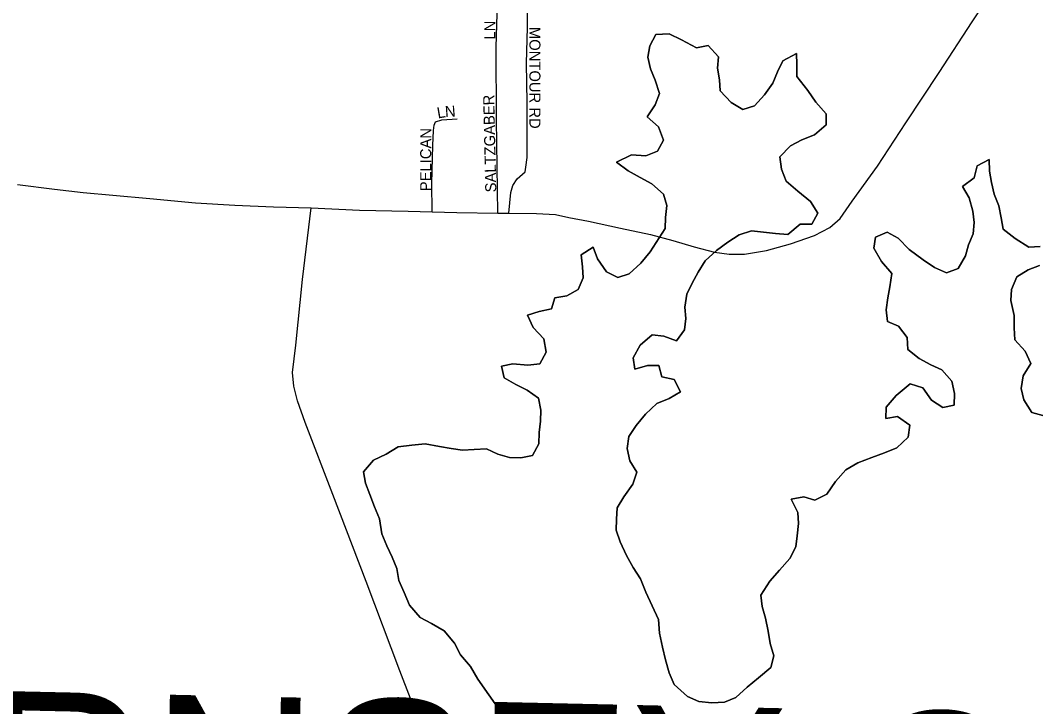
# Model space of a CAD drawing. Extents: x -22 to 431, y -18 to 160.
# Drawn here: x 329.532 to 330.402, y 158.932 to 159.52 of the extents above; entities that cross this region are included whole.
import ezdxf

# ---------------------------------------------------------------- set-up
doc = ezdxf.new("R2010")
doc.units = 0
for name, color, linetype in [('GM_X_County_ROW', 7, 'Continuous'), ('GM_X_County_Subdivision', 7, 'Continuous'), ('GM_X_Township_ROW', 7, 'Continuous'), ('GM_X_Township_Subdivision', 7, 'Continuous'), ('GM_X_Unincorporated_Text', 7, 'Continuous')]:
    doc.layers.add(name, color=color, linetype=linetype)

msp = doc.modelspace()

# ---------------------------------------------------------------- linework, layer by layer
at = {"layer": 'GM_X_County_ROW'}
for points in [[(329.52949, 159.37947), (329.56105, 159.37544), (329.58577, 159.37243), (329.61124, 159.37019), (329.64279, 159.36729), (329.68194, 159.36377), (329.71575, 159.36167), (329.74879, 159.36031), (329.78107, 159.35933), (329.82247, 159.35735), (329.86423, 159.35653), (329.88487, 159.35593), (329.906, 159.35532), (329.94107, 159.35479), (329.94206, 159.35478), (329.95051, 159.35472), (329.97432, 159.35455), (329.99065, 159.35368), (330.00208, 159.35121), (330.01884, 159.34807), (330.04626, 159.34206), (330.07217, 159.33641), (330.09123, 159.33141), (330.10954, 159.32601), (330.12707, 159.32136), (330.13963, 159.31967), (330.15254, 159.3195), (330.17145, 159.32286), (330.19223, 159.32852), (330.2126, 159.33569), (330.22577, 159.34237), (330.23475, 159.35011), (330.24512, 159.3651), (330.26661, 159.39509), (330.29103, 159.43234), (330.31951, 159.47537), (330.34799, 159.51877), (330.37389, 159.55795)], [(329.94924, 158.73153), (329.93725, 158.76413), (329.91055, 158.8213), (329.88469, 158.89114), (329.85729, 158.96248), (329.82828, 159.03911), (329.79969, 159.11347), (329.77586, 159.17537), (329.76947, 159.19388), (329.76622, 159.20636), (329.76526, 159.21813), (329.76789, 159.24172), (329.77376, 159.29804), (329.78107, 159.35933)]]:
    msp.add_lwpolyline(points, dxfattribs=at)
at = {"layer": 'GM_X_Township_ROW'}
for points in [[(329.95051, 159.35472), (329.95222, 159.37239), (329.95406, 159.37847), (329.95779, 159.38419), (329.96455, 159.39032), (329.96526, 159.39412), (329.96641, 159.40251), (329.96629, 159.44967), (329.9657, 159.48326), (329.9666, 159.51403), (329.96672, 159.5657), (329.96671, 159.58067), (329.96681, 159.5969), (329.96693, 159.59938), (329.97924, 159.60181), (329.99294, 159.60755), (329.99854, 159.61595), (330.00001, 159.62127)], [(329.94107, 159.35479), (329.93997, 159.43489), (329.93983, 159.49711), (329.94161, 159.55478), (329.94237, 159.59767), (329.89359, 159.59955), (329.89359, 159.55554), (329.94123, 159.55478)], [(329.88487, 159.35593), (329.88449, 159.38057), (329.88535, 159.41283), (329.886, 159.42573), (329.88671, 159.43029), (329.88782, 159.43296), (329.8931, 159.43489), (329.90632, 159.43576)]]:
    msp.add_lwpolyline(points, dxfattribs=at)
at = {"layer": 'GM_X_Township_Subdivision'}
for points in [[(330.18554, 159.48538), (330.1811, 159.47584), (330.17704, 159.46631), (330.16995, 159.45636), (330.16135, 159.44677), (330.15117, 159.44361), (330.14127, 159.44956), (330.13171, 159.45968), (330.13123, 159.46915), (330.12961, 159.479), (330.13026, 159.48886), (330.12145, 159.49862), (330.11164, 159.4966), (330.0987, 159.50326), (330.08805, 159.50844), (330.07671, 159.50792), (330.07151, 159.49838), (330.06973, 159.48849), (330.0721, 159.47866), (330.07599, 159.46885), (330.0799, 159.45752), (330.07622, 159.44761), (330.06914, 159.43728), (330.07907, 159.42868), (330.08335, 159.41736), (330.07816, 159.40781), (330.06798, 159.40389), (330.05586, 159.40488), (330.04306, 159.39865), (330.05298, 159.39119), (330.06326, 159.38525), (330.07315, 159.38006), (330.08309, 159.37108), (330.08622, 159.36126), (330.08481, 159.351), (330.08454, 159.34152), (330.07188, 159.32164), (330.06366, 159.31206), (330.05392, 159.30283), (330.04412, 159.29968), (330.03423, 159.30448), (330.02654, 159.31577), (330.02303, 159.32558), (330.01251, 159.31901), (330.01376, 159.30878), (330.01424, 159.29931), (330.01018, 159.28939), (330.0004, 159.28396), (329.9902, 159.28232), (329.98728, 159.2728), (329.97671, 159.2704), (329.96653, 159.26724), (329.97156, 159.25668), (329.98074, 159.24693), (329.98275, 159.23558), (329.97718, 159.22565), (329.96698, 159.22438), (329.9541, 159.22574), (329.94429, 159.22372), (329.94667, 159.21351), (329.95656, 159.20795), (329.96645, 159.20314), (329.97598, 159.19605), (329.97798, 159.18584), (329.97771, 159.17635), (329.97667, 159.16686), (329.9764, 159.157), (329.97083, 159.14707), (329.96101, 159.14505), (329.95117, 159.14531), (329.94131, 159.14822), (329.93142, 159.15264), (329.92083, 159.15213), (329.911, 159.15163), (329.90115, 159.15303), (329.89129, 159.1548), (329.87878, 159.15692), (329.86744, 159.15602), (329.85573, 159.15436), (329.84558, 159.14817), (329.83466, 159.1431), (329.82607, 159.13313), (329.82769, 159.12329), (329.83157, 159.11348), (329.83547, 159.10291), (329.83974, 159.09272), (329.84177, 159.07985), (329.84604, 159.06967), (329.85068, 159.05986), (329.85457, 159.05005), (329.85619, 159.03983), (329.86084, 159.02965), (329.8655, 159.01872), (329.87469, 159.00821), (329.8842, 159.00302), (329.89524, 158.99671), (329.90406, 158.9862), (329.90908, 158.97602), (329.91789, 158.96627), (329.92406, 158.95535), (329.94288, 158.92828)], [(329.94288, 158.92828), (329.92406, 158.95535), (329.91789, 158.96627), (329.90908, 158.97602), (329.90406, 158.9862), (329.89524, 158.99671), (329.8842, 159.00302), (329.87469, 159.00821), (329.8655, 159.01872), (329.86084, 159.02965), (329.85619, 159.03983), (329.85457, 159.05005), (329.85068, 159.05986), (329.84604, 159.06967), (329.84177, 159.07985), (329.83974, 159.09272), (329.83547, 159.10291), (329.83157, 159.11348), (329.82769, 159.12329), (329.82607, 159.13313), (329.83466, 159.1431), (329.84558, 159.14817), (329.85573, 159.15436), (329.86744, 159.15602), (329.87878, 159.15692), (329.89129, 159.1548), (329.90115, 159.15303), (329.911, 159.15163), (329.92083, 159.15213), (329.93142, 159.15264), (329.94131, 159.14822), (329.95117, 159.14531), (329.96101, 159.14505), (329.97083, 159.14707), (329.9764, 159.157), (329.97667, 159.16686), (329.97771, 159.17635), (329.97798, 159.18584), (329.97598, 159.19605), (329.96645, 159.20314), (329.95656, 159.20795), (329.94667, 159.21351), (329.94429, 159.22372), (329.9541, 159.22574), (329.96698, 159.22438), (329.97718, 159.22565), (329.98275, 159.23558), (329.98074, 159.24693), (329.97156, 159.25668), (329.96653, 159.26724), (329.97671, 159.2704), (329.98728, 159.2728), (329.9902, 159.28232), (330.0004, 159.28396), (330.01018, 159.28939), (330.01424, 159.29931), (330.01376, 159.30878), (330.01251, 159.31901), (330.02303, 159.32558), (330.02654, 159.31577), (330.03423, 159.30448), (330.04412, 159.29968), (330.05392, 159.30283), (330.06366, 159.31206), (330.07188, 159.32164), (330.08454, 159.34152), (330.08481, 159.351), (330.08622, 159.36126), (330.08309, 159.37108), (330.07315, 159.38006), (330.06326, 159.38525), (330.05298, 159.39119), (330.04306, 159.39865), (330.05586, 159.40488), (330.06798, 159.40389), (330.07816, 159.40781), (330.08335, 159.41736), (330.07907, 159.42868), (330.06914, 159.43728), (330.07622, 159.44761), (330.0799, 159.45752), (330.07599, 159.46885), (330.0721, 159.47866), (330.06973, 159.48849), (330.07151, 159.49838), (330.07671, 159.50792), (330.08805, 159.50844), (330.0987, 159.50326), (330.11164, 159.4966), (330.12145, 159.49862), (330.13026, 159.48886), (330.12961, 159.479), (330.13123, 159.46915), (330.13171, 159.45968), (330.14127, 159.44956), (330.15117, 159.44361), (330.16135, 159.44677), (330.16995, 159.45636), (330.17704, 159.46631), (330.1811, 159.47584), (330.18554, 159.48538)], [(330.29443, 159.17307), (330.29302, 159.16282), (330.28328, 159.15359), (330.27274, 159.14929), (330.2618, 159.14536), (330.24975, 159.14066), (330.23959, 159.13485), (330.23062, 159.12488), (330.22317, 159.11379), (330.21301, 159.10873), (330.20352, 159.11165), (330.19257, 159.10962), (330.19836, 159.09831), (330.19884, 159.08884), (330.19782, 159.07821), (330.19679, 159.06871), (330.19159, 159.05879), (330.18262, 159.04882), (330.1744, 159.03924), (330.16658, 159.02738), (330.16782, 159.01754), (330.17057, 159.00771), (330.17296, 158.99636), (330.17459, 158.98577), (330.17773, 158.97519), (330.17518, 158.9653), (330.16468, 158.95644), (330.15493, 158.94836), (330.14519, 158.93952), (330.13539, 158.9356), (330.1248, 158.93509), (330.11344, 158.93609), (330.10393, 158.94052), (330.09248, 158.95062), (330.08821, 158.9608), (330.08506, 158.97176), (330.0823, 158.98273), (330.0799, 158.99483), (330.07902, 159.00657), (330.06818, 159.02995), (330.06352, 159.04127), (330.05736, 159.05106), (330.05157, 159.06122), (330.04615, 159.07291), (330.04264, 159.08311), (330.04292, 159.09259), (330.04357, 159.10208), (330.04915, 159.11163), (330.05698, 159.12235), (330.06028, 159.13263), (330.0545, 159.14242), (330.05211, 159.153), (330.05352, 159.16326), (330.05985, 159.17282), (330.06769, 159.1824), (330.07743, 159.19162), (330.08798, 159.19593), (330.09775, 159.20174), (330.09235, 159.21229), (330.08173, 159.21443), (330.07935, 159.22426), (330.06952, 159.22414), (330.05858, 159.22097), (330.05734, 159.23082), (330.06328, 159.24151), (330.0734, 159.25036), (330.08363, 159.24935), (330.09426, 159.24531), (330.10135, 159.25488), (330.10238, 159.26437), (330.10152, 159.27422), (330.1033, 159.28524), (330.10774, 159.29478), (330.11293, 159.30432), (330.11888, 159.31388), (330.12863, 159.32272), (330.13839, 159.33005), (330.14816, 159.33624), (330.15871, 159.33978), (330.16894, 159.33839), (330.17917, 159.33738), (330.18977, 159.33637), (330.20028, 159.34523), (330.21049, 159.34536), (330.21568, 159.3549), (330.20915, 159.36468), (330.19846, 159.37365), (330.18853, 159.38225), (330.18426, 159.39244), (330.18301, 159.40304), (330.19199, 159.41264), (330.20177, 159.41769), (330.2127, 159.422), (330.22282, 159.43047), (330.22272, 159.43995), (330.21391, 159.45008), (330.207, 159.45985), (330.19741, 159.47187), (330.19768, 159.48211), (330.1972, 159.49159), (330.18554, 159.48538)], [(330.18554, 159.48538), (330.1972, 159.49159), (330.19768, 159.48211), (330.19741, 159.47187), (330.207, 159.45985), (330.21391, 159.45008), (330.22272, 159.43995), (330.22282, 159.43047), (330.2127, 159.422), (330.20177, 159.41769), (330.19199, 159.41264), (330.18301, 159.40304), (330.18426, 159.39244), (330.18853, 159.38225), (330.19846, 159.37365), (330.20915, 159.36468), (330.21568, 159.3549), (330.21049, 159.34536), (330.20028, 159.34523), (330.18977, 159.33637), (330.17917, 159.33738), (330.16894, 159.33839), (330.15871, 159.33978), (330.14816, 159.33624), (330.13839, 159.33005), (330.12863, 159.32272), (330.11888, 159.31388), (330.11293, 159.30432), (330.10774, 159.29478), (330.1033, 159.28524), (330.10152, 159.27422), (330.10238, 159.26437), (330.10135, 159.25488), (330.09426, 159.24531), (330.08363, 159.24935), (330.0734, 159.25036), (330.06328, 159.24151), (330.05734, 159.23082), (330.05858, 159.22097), (330.06952, 159.22414), (330.07935, 159.22426), (330.08173, 159.21443), (330.09235, 159.21229), (330.09775, 159.20174), (330.08798, 159.19593), (330.07743, 159.19162), (330.06769, 159.1824), (330.05985, 159.17282), (330.05352, 159.16326), (330.05211, 159.153), (330.0545, 159.14242), (330.06028, 159.13263), (330.05698, 159.12235), (330.04915, 159.11163), (330.04357, 159.10208), (330.04292, 159.09259), (330.04264, 159.08311), (330.04615, 159.07291), (330.05157, 159.06122), (330.05736, 159.05106), (330.06352, 159.04127), (330.06818, 159.02995), (330.07902, 159.00657), (330.0799, 158.99483), (330.0823, 158.98273), (330.08506, 158.97176), (330.08821, 158.9608), (330.09248, 158.95062), (330.10393, 158.94052), (330.11344, 158.93609), (330.1248, 158.93509), (330.13539, 158.9356), (330.14519, 158.93952), (330.15493, 158.94836), (330.16468, 158.95644), (330.17518, 158.9653), (330.17773, 158.97519), (330.17459, 158.98577), (330.17296, 158.99636), (330.17057, 159.00771), (330.16782, 159.01754), (330.16658, 159.02738), (330.1744, 159.03924), (330.18262, 159.04882), (330.19159, 159.05879), (330.19679, 159.06871), (330.19782, 159.07821), (330.19884, 159.08884), (330.19836, 159.09831), (330.19257, 159.10962), (330.20352, 159.11165), (330.21301, 159.10873), (330.22317, 159.11379), (330.23062, 159.12488), (330.23959, 159.13485), (330.24975, 159.14066), (330.2618, 159.14536), (330.27274, 159.14929), (330.28328, 159.15359), (330.29302, 159.16282), (330.29443, 159.17307)], [(330.4063, 159.32616), (330.39647, 159.32566), (330.38466, 159.3331), (330.37436, 159.34094), (330.37274, 159.35078), (330.37074, 159.361), (330.36685, 159.37119), (330.36448, 159.38102), (330.36286, 159.39086), (330.36237, 159.40071), (330.35222, 159.39528), (330.34968, 159.38501), (330.33954, 159.37768), (330.34532, 159.36789), (330.34847, 159.35655), (330.34971, 159.3467), (330.34867, 159.33721), (330.34461, 159.32767), (330.34207, 159.31816), (330.33575, 159.30746), (330.32595, 159.30355), (330.31569, 159.30835), (330.30578, 159.31468), (330.29396, 159.32363), (330.2844, 159.33338), (330.27488, 159.33857), (330.26509, 159.33427), (330.26368, 159.32478), (330.27023, 159.31348), (330.27904, 159.30297), (330.27728, 159.29157), (330.27548, 159.28207), (330.27408, 159.27181), (330.27532, 159.26196), (330.28482, 159.25791), (330.29211, 159.24814), (330.2926, 159.2379), (330.30252, 159.23006), (330.31242, 159.22488), (330.32192, 159.22044), (330.33035, 159.21069), (330.33273, 159.2001), (330.33246, 159.19023), (330.32264, 159.18821), (330.31312, 159.19454), (330.30544, 159.20507), (330.29481, 159.20835), (330.28281, 159.19834), (330.27421, 159.18837), (330.27393, 159.17889), (330.28375, 159.18053), (330.29443, 159.17307)], [(330.29443, 159.17307), (330.28375, 159.18053), (330.27393, 159.17889), (330.27421, 159.18837), (330.28281, 159.19834), (330.29481, 159.20835), (330.30544, 159.20507), (330.31312, 159.19454), (330.32264, 159.18821), (330.33246, 159.19023), (330.33273, 159.2001), (330.33035, 159.21069), (330.32192, 159.22044), (330.31242, 159.22488), (330.30252, 159.23006), (330.2926, 159.2379), (330.29211, 159.24814), (330.28482, 159.25791), (330.27532, 159.26196), (330.27408, 159.27181), (330.27548, 159.28207), (330.27728, 159.29157), (330.27904, 159.30297), (330.27023, 159.31348), (330.26368, 159.32478), (330.26509, 159.33427), (330.27488, 159.33857), (330.2844, 159.33338), (330.29396, 159.32363), (330.30578, 159.31468), (330.31569, 159.30835), (330.32595, 159.30355), (330.33575, 159.30746), (330.34207, 159.31816), (330.34461, 159.32767), (330.34867, 159.33721), (330.34971, 159.3467), (330.34847, 159.35655), (330.34532, 159.36789), (330.33954, 159.37768), (330.34968, 159.38501), (330.35222, 159.39528), (330.36237, 159.40071), (330.36286, 159.39086), (330.36448, 159.38102), (330.36685, 159.37119), (330.37074, 159.361), (330.37274, 159.35078), (330.37436, 159.34094), (330.38466, 159.3331), (330.39647, 159.32566), (330.4063, 159.32616)], [(330.4086, 159.18131), (330.39912, 159.18385), (330.39219, 159.19476), (330.38982, 159.2046), (330.3916, 159.21524), (330.39829, 159.22594), (330.39326, 159.2365), (330.38445, 159.24625), (330.38396, 159.25648), (330.38385, 159.2671), (330.38107, 159.27996), (330.38172, 159.28945), (330.38615, 159.30012), (330.39592, 159.30631), (330.40572, 159.30985)], [(330.40572, 159.30985), (330.39592, 159.30631), (330.38615, 159.30012), (330.38172, 159.28945), (330.38107, 159.27996), (330.38385, 159.2671), (330.38396, 159.25648), (330.38445, 159.24625), (330.39326, 159.2365), (330.39829, 159.22594), (330.3916, 159.21524), (330.38982, 159.2046), (330.39219, 159.19476), (330.39912, 159.18385), (330.4086, 159.18131)]]:
    msp.add_lwpolyline(points, dxfattribs=at)

# ---------------------------------------------------------------- texts
at = {"layer": 'GM_X_County_Subdivision'}
for s, rotation, p in [('LN', 90, (329.93908, 159.50362)), ('MONTOUR RD', 270, (329.96824, 159.51445)), ('SALTZGABER', 91.28717, (329.93992, 159.37273)), ('N', 4.17907, (329.89618, 159.43704)), ('L', 9.84415, (329.88986, 159.43593)), ('PELICAN', 90, (329.88408, 159.37362))]:
    msp.add_text(s, height=0.00947, rotation=rotation, dxfattribs=at).set_placement(p)
at = {"layer": 'GM_X_Unincorporated_Text'}
msp.add_text('GUERNSEY COUNTY', height=0.15, rotation=358.733, dxfattribs=at).set_placement((329.0609, 158.80518))

doc.saveas('drawing.dxf')
